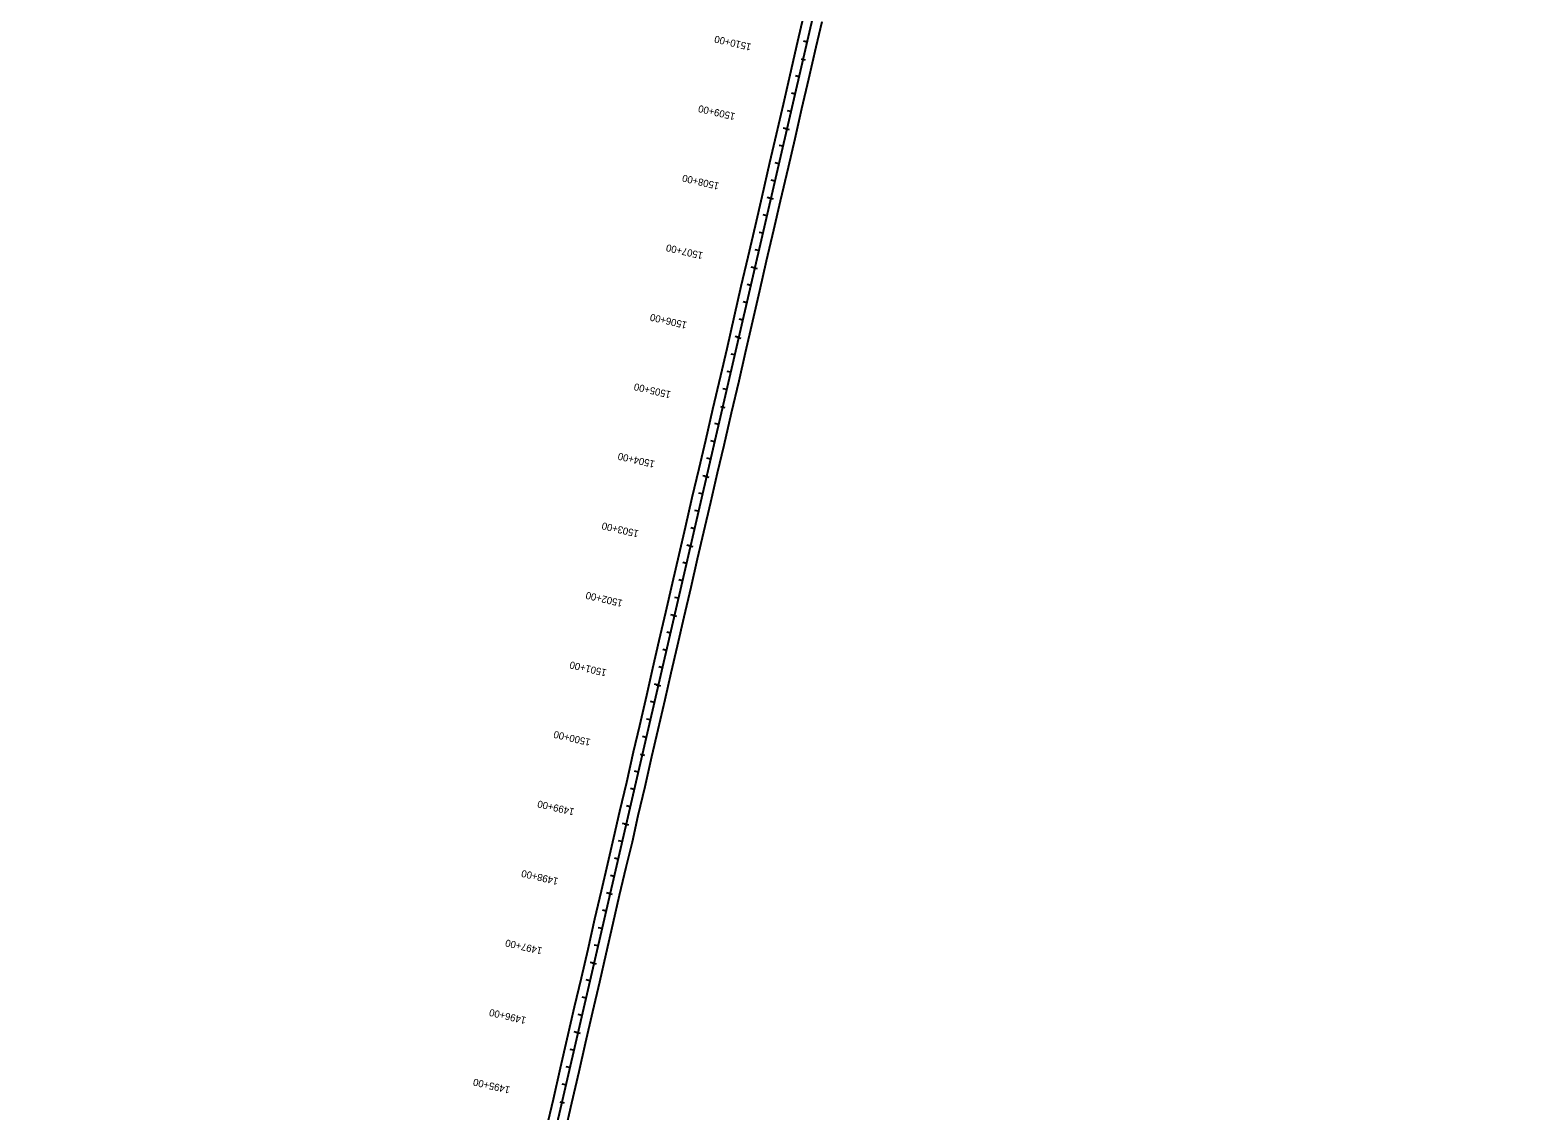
# Model space of a CAD drawing. Extents: x 21596470 to 21601942, y 8263806 to 8275912.
# Drawn here: x 21596601 to 21598714, y 8269862 to 8271376 of the extents above; entities that cross this region are included whole.
import ezdxf

# ---------------------------------------------------------------- set-up
doc = ezdxf.new("R2010")
doc.units = 0
for name, color, linetype in [('Level 1', 7, 'Continuous'), ('Level 20', 7, 'Continuous'), ('SurTxtLeaderLine', 7, 'Continuous'), ('SurTxtSurveyInformation', 7, 'Continuous'), ('wetNoteSoil', 7, 'Continuous')]:
    doc.layers.add(name, color=color, linetype=linetype)

msp = doc.modelspace()

# ---------------------------------------------------------------- linework, layer by layer
at = {"layer": 'Level 1'}
for p, q in [((21597681.7, 8271335.5), (21597687.7, 8271334.2)), ((21597662.2, 8271237.4), (21597656.8, 8271238.6)), ((21597639.6, 8271140), (21597634.3, 8271141.2)), ((21597617.1, 8271042.6), (21597611.8, 8271043.8)), ((21597594.5, 8270945.1), (21597589.2, 8270946.4)), ((21597569, 8270848.4), (21597575, 8270847)), ((21597549.5, 8270750.3), (21597544.2, 8270751.5)), ((21597526.9, 8270652.9), (21597521.6, 8270654.1)), ((21597504.4, 8270555.4), (21597499.1, 8270556.7)), ((21597481.9, 8270458), (21597476.5, 8270459.2)), ((21597456.3, 8270361.3), (21597462.3, 8270359.9)), ((21597436.8, 8270263.1), (21597431.5, 8270264.4)), ((21597414.2, 8270165.7), (21597408.9, 8270167)), ((21597391.7, 8270068.3), (21597386.4, 8270069.5)), ((21597369.2, 8269970.9), (21597363.8, 8269972.1)), ((21597343.6, 8269874.1), (21597349.6, 8269872.8))]:
    msp.add_line(p, q, dxfattribs=at)
at = {"layer": 'Level 20'}
for p, q in [((21596601.4, 8266652.3), (21598714.2, 8275785)), ((21596728.7, 8267202.6), (21598588.8, 8275242.6))]:
    msp.add_line(p, q, dxfattribs=at)
at = {"layer": 'SurTxtLeaderLine'}
msp.add_lwpolyline([(21597350.5, 8269829.6), (21597360.5, 8269872.9), (21597370.6, 8269916.6), (21597379.8, 8269956.3), (21597389.9, 8270000.7), (21597399.6, 8270042.5), (21597408.7, 8270081.6), (21597418.4, 8270124.3), (21597427.4, 8270163.8), (21597436.6, 8270202.8), (21597445.3, 8270238.7), (21597453.5, 8270275.4), (21597463.1, 8270316.1), (21597472.7, 8270358.1), (21597481.4, 8270395.7), (21597491.1, 8270437.9), (21597499.9, 8270475.3), (21597508.6, 8270513.2), (21597517.8, 8270553.8), (21597527.5, 8270595.3), (21597536.6, 8270635), (21597545.4, 8270672.9), (21597555.1, 8270714.6), (21597564.8, 8270755.6), (21597573.8, 8270794.1), (21597584.2, 8270839.4), (21597594.8, 8270884.3), (21597604.1, 8270924), (21597614.2, 8270968.7), (21597623.9, 8271011.1), (21597633.5, 8271052.5), (21597643.4, 8271096.1), (21597652.8, 8271136.7), (21597663.9, 8271184), (21597673.3, 8271224.2), (21597682.9, 8271265.9), (21597692.5, 8271307.8), (21597702.9, 8271352.7), (21597711.1, 8271388.2)], dxfattribs=at)
at = {"layer": 'SurTxtSurveyInformation'}
msp.add_lwpolyline([(21597324.9, 8269836.6), (21597334.6, 8269877.9), (21597344.6, 8269921.7), (21597354, 8269962.3), (21597364.4, 8270007.3), (21597374, 8270047.8), (21597383.3, 8270088.3), (21597392.9, 8270130.7), (21597401.9, 8270169.7), (21597410.8, 8270208.3), (21597419.3, 8270244.7), (21597427.8, 8270281.4), (21597437.4, 8270322.3), (21597447, 8270364.8), (21597455.7, 8270401.7), (21597465.6, 8270444), (21597474.2, 8270481.6), (21597483.1, 8270520.5), (21597492.4, 8270560.5), (21597501.8, 8270600.9), (21597510.9, 8270641.1), (21597519.8, 8270679.6), (21597529.2, 8270720.9), (21597538.9, 8270761.8), (21597548.1, 8270801.1), (21597558.2, 8270844.6), (21597569.3, 8270891.8), (21597578.1, 8270929.8), (21597588.3, 8270975.5), (21597597.8, 8271017.1), (21597607.4, 8271058.4), (21597617.9, 8271102.1), (21597627.1, 8271142.9), (21597638.1, 8271190.4), (21597647.3, 8271230), (21597656.9, 8271272.3), (21597666.6, 8271313.4), (21597677.4, 8271360.4), (21597685.2, 8271394.3)], dxfattribs=at)
at = {"layer": 'wetNoteSoil'}
for p, q in [((21597690.3, 8271359.2), (21597685, 8271360.4)), ((21597681.7, 8271335.5), (21597687.7, 8271334.2)), ((21597679.1, 8271310.5), (21597673.8, 8271311.7)), ((21597673.4, 8271286.1), (21597668.1, 8271287.4)), ((21597667.8, 8271261.8), (21597662.5, 8271263)), ((21597659.2, 8271238.1), (21597665.1, 8271236.7)), ((21597656.5, 8271213.1), (21597651.2, 8271214.3)), ((21597650.9, 8271188.7), (21597645.6, 8271189.9)), ((21597645.3, 8271164.3), (21597639.9, 8271165.6)), ((21597636.6, 8271140.7), (21597642.6, 8271139.3)), ((21597634, 8271115.6), (21597628.7, 8271116.9)), ((21597628.4, 8271091.3), (21597623, 8271092.5)), ((21597622.7, 8271066.9), (21597617.4, 8271068.2)), ((21597614.1, 8271043.3), (21597620.1, 8271041.9)), ((21597611.5, 8271018.2), (21597606.1, 8271019.4)), ((21597605.8, 8270993.9), (21597600.5, 8270995.1)), ((21597600.2, 8270969.5), (21597594.9, 8270970.7)), ((21597591.6, 8270945.8), (21597597.5, 8270944.4)), ((21597588.9, 8270920.8), (21597583.6, 8270922)), ((21597583.3, 8270896.4), (21597578, 8270897.7)), ((21597577.6, 8270872.1), (21597572.3, 8270873.3)), ((21597569, 8270848.4), (21597575, 8270847)), ((21597566.4, 8270823.4), (21597561.1, 8270824.6)), ((21597560.7, 8270799), (21597555.4, 8270800.2)), ((21597555.1, 8270774.6), (21597549.8, 8270775.9)), ((21597546.5, 8270751), (21597552.5, 8270749.6)), ((21597543.8, 8270725.9), (21597538.5, 8270727.2)), ((21597538.2, 8270701.6), (21597532.9, 8270702.8)), ((21597532.6, 8270677.2), (21597527.2, 8270678.4)), ((21597523.9, 8270653.5), (21597529.9, 8270652.2)), ((21597521.3, 8270628.5), (21597516, 8270629.7)), ((21597515.7, 8270604.1), (21597510.3, 8270605.4)), ((21597510, 8270579.8), (21597504.7, 8270581)), ((21597501.4, 8270556.1), (21597507.4, 8270554.7)), ((21597498.8, 8270531.1), (21597493.4, 8270532.3)), ((21597493.1, 8270506.7), (21597487.8, 8270507.9)), ((21597487.5, 8270482.4), (21597482.2, 8270483.6)), ((21597478.9, 8270458.7), (21597484.8, 8270457.3)), ((21597476.2, 8270433.6), (21597470.9, 8270434.9)), ((21597470.6, 8270409.3), (21597465.3, 8270410.5)), ((21597464.9, 8270384.9), (21597459.6, 8270386.2)), ((21597456.3, 8270361.3), (21597462.3, 8270359.9)), ((21597453.7, 8270336.2), (21597448.4, 8270337.5)), ((21597448, 8270311.9), (21597442.7, 8270313.1)), ((21597442.4, 8270287.5), (21597437.1, 8270288.7)), ((21597433.8, 8270263.8), (21597439.8, 8270262.5)), ((21597431.1, 8270238.8), (21597425.8, 8270240)), ((21597425.5, 8270214.4), (21597420.2, 8270215.7)), ((21597419.9, 8270190.1), (21597414.5, 8270191.3)), ((21597411.3, 8270166.4), (21597417.2, 8270165)), ((21597408.6, 8270141.4), (21597403.3, 8270142.6)), ((21597403, 8270117), (21597397.6, 8270118.2)), ((21597397.3, 8270092.7), (21597392, 8270093.9)), ((21597388.7, 8270069), (21597394.7, 8270067.6)), ((21597386.1, 8270043.9), (21597380.7, 8270045.2)), ((21597380.4, 8270019.6), (21597375.1, 8270020.8)), ((21597374.8, 8269995.2), (21597369.5, 8269996.5)), ((21597366.2, 8269971.6), (21597372.1, 8269970.2)), ((21597363.5, 8269946.5), (21597358.2, 8269947.7)), ((21597357.9, 8269922.2), (21597352.6, 8269923.4)), ((21597352.3, 8269897.8), (21597346.9, 8269899)), ((21597343.6, 8269874.1), (21597349.6, 8269872.8))]:
    msp.add_line(p, q, dxfattribs=at)

# ---------------------------------------------------------------- texts
at = {"layer": 'Level 1'}
for s, p in [('1510+00', (21597612.8, 8271356.6)), ('1505+00', (21597500.1, 8270869.5)), ('1500+00', (21597387.4, 8270382.4)), ('1495+00', (21597274.7, 8269895.2))]:
    msp.add_text(s, height=10.02, rotation=166.974, dxfattribs=at).set_placement(p)
at = {"layer": 'wetNoteSoil'}
for s, p in [('1510+00', (21597612.8, 8271356.6)), ('1509+00', (21597590.2, 8271259.2)), ('1508+00', (21597567.7, 8271161.8)), ('1507+00', (21597545.1, 8271064.3)), ('1506+00', (21597522.6, 8270966.9)), ('1505+00', (21597500.1, 8270869.5)), ('1504+00', (21597477.5, 8270772.1)), ('1503+00', (21597455, 8270674.6)), ('1502+00', (21597432.5, 8270577.2)), ('1501+00', (21597409.9, 8270479.8)), ('1500+00', (21597387.4, 8270382.4)), ('1499+00', (21597364.8, 8270284.9)), ('1498+00', (21597342.3, 8270187.5)), ('1497+00', (21597319.8, 8270090.1)), ('1496+00', (21597297.2, 8269992.7)), ('1495+00', (21597274.7, 8269895.2))]:
    msp.add_text(s, height=10.02, rotation=166.974, dxfattribs=at).set_placement(p)

doc.saveas('drawing.dxf')
